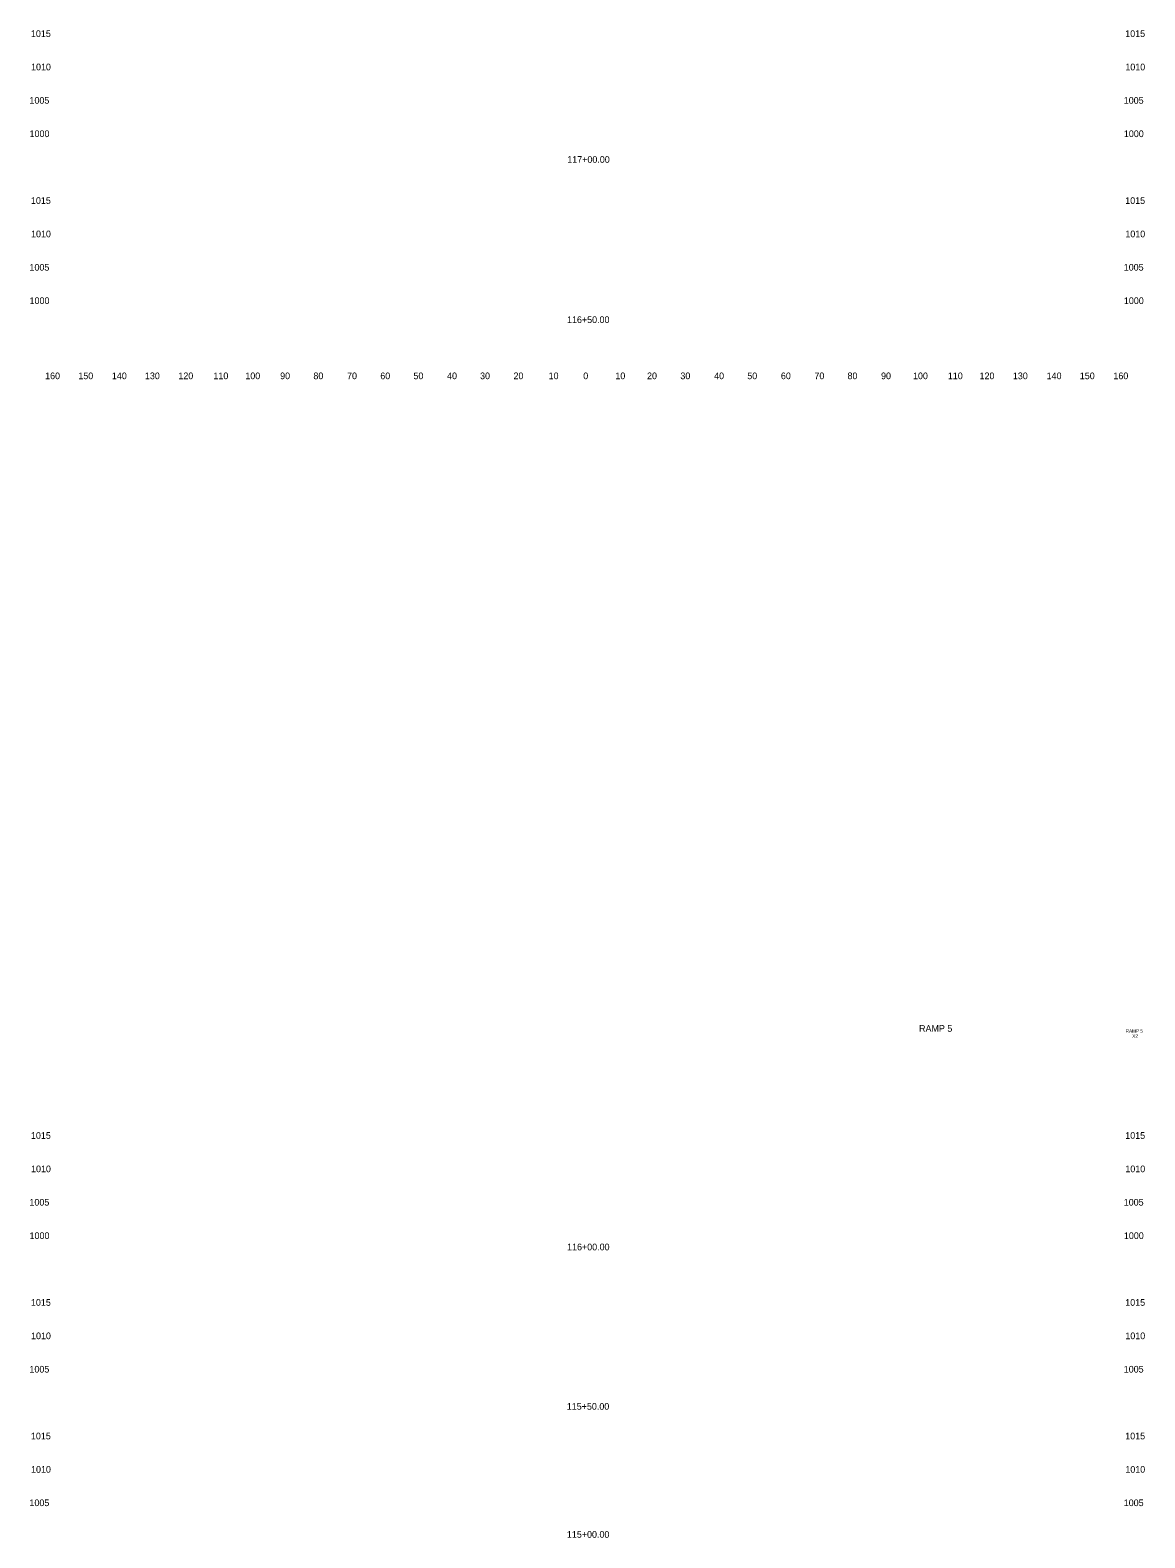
# Model space of a CAD drawing. Extents: x 4994 to 5842, y 4997 to 8804.
# Drawn here: x 4993.6 to 5327.5, y 5450.5 to 5902 of the extents above; entities that cross this region are included whole.
import ezdxf

# ---------------------------------------------------------------- set-up
doc = ezdxf.new("R2010")
doc.units = 0
for name, color, linetype in [('CLS_Search_Dist', 7, 'Continuous'), ('RD_XE_Ground', 7, 'Continuous'), ('UC_PD_Text', 7, 'Continuous')]:
    doc.layers.add(name, color=color, linetype=linetype)

msp = doc.modelspace()

# ---------------------------------------------------------------- texts
at = {"layer": 'CLS_Search_Dist'}
for s, p in [('1015', (4993.85, 5900)), ('1015', (5321.65, 5900)), ('1010', (4993.88, 5890)), ('1010', (5321.68, 5890)), ('1005', (4993.4, 5880)), ('1005', (5321.2, 5880)), ('1000', (4993.44, 5870)), ('1000', (5321.24, 5870)), ('1015', (4993.85, 5850)), ('1015', (5321.65, 5850)), ('1010', (4993.88, 5840)), ('1010', (5321.68, 5840)), ('1005', (4993.4, 5830)), ('1005', (5321.2, 5830)), ('1000', (4993.44, 5820)), ('1000', (5321.24, 5820)), ('160', (4998.1, 5797.5)), ('150', (5008.04, 5797.5)), ('140', (5018.1, 5797.5)), ('130', (5027.99, 5797.5)), ('120', (5038.01, 5797.5)), ('110', (5048.51, 5797.5)), ('100', (5058.07, 5797.5)), ('90', (5068.5, 5797.5)), ('80', (5078.46, 5797.5)), ('70', (5088.54, 5797.5)), ('60', (5098.5, 5797.5)), ('50', (5108.43, 5797.5)), ('40', (5118.5, 5797.5)), ('30', (5128.39, 5797.5)), ('20', (5138.4, 5797.5)), ('10', (5148.91, 5797.5)), ('0', (5159.3, 5797.5)), ('0', (5159.3, 5797.5)), ('10', (5168.91, 5797.5)), ('20', (5178.4, 5797.5)), ('30', (5188.39, 5797.5)), ('40', (5198.5, 5797.5)), ('50', (5208.43, 5797.5)), ('60', (5218.5, 5797.5)), ('70', (5228.54, 5797.5)), ('80', (5238.46, 5797.5)), ('90', (5248.5, 5797.5)), ('100', (5258.07, 5797.5)), ('110', (5268.51, 5797.5)), ('120', (5278.01, 5797.5)), ('130', (5287.99, 5797.5)), ('140', (5298.1, 5797.5)), ('150', (5308.04, 5797.5)), ('160', (5318.1, 5797.5)), ('1015', (4993.85, 5570)), ('1015', (5321.65, 5570)), ('1010', (4993.88, 5560)), ('1010', (5321.68, 5560)), ('1005', (4993.4, 5550)), ('1005', (5321.2, 5550)), ('1000', (4993.44, 5540)), ('1000', (5321.24, 5540)), ('1015', (4993.85, 5520)), ('1015', (5321.65, 5520)), ('1010', (4993.88, 5510)), ('1010', (5321.68, 5510)), ('1005', (4993.4, 5500)), ('1005', (5321.2, 5500)), ('1015', (4993.85, 5480)), ('1015', (5321.65, 5480)), ('1010', (4993.88, 5470)), ('1010', (5321.68, 5470)), ('1005', (4993.4, 5460)), ('1005', (5321.2, 5460))]:
    msp.add_text(s, height=2, dxfattribs=at).set_placement(p)
at = {"layer": 'RD_XE_Ground'}
for s, p in [('117+00.00', (5154.51, 5862.3)), ('116+50.00', (5154.43, 5814.31)), ('116+00.00', (5154.46, 5536.62)), ('115+50.00', (5154.37, 5488.87)), ('115+00.00', (5154.4, 5450.53))]:
    msp.add_text(s, height=2, dxfattribs=at).set_placement(p)
at = {"layer": 'UC_PD_Text'}
for s, height, p in [('RAMP 5', 2, (5259.89, 5602.06)), ('RAMP 5', 1, (5321.78, 5601.8)), ('X2', 1, (5323.74, 5600.3))]:
    msp.add_text(s, height=height, dxfattribs=at).set_placement(p)

doc.saveas('drawing.dxf')
